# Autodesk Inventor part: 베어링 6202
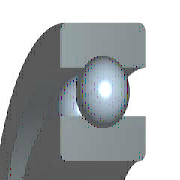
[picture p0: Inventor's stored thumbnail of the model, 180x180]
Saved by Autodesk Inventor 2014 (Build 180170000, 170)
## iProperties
IsCustomPart: 1
Created: 2015-09
Part Number: 베어링 6202
Material: 강철, 연강
Description: 깊은 그루브 볼 베어링
Document SubType Name: Modeling
Standard: KS B 2023
Designer: mduedu
Standards Organization: KS
Language: ko-KR
Size Designation: 6202 - 15 x 35 x 11
Categories: <MemberInstance><Categories><Category DisplayName="샤프트 부품" InternalName="7f7aeb1f-a693-4053-b835-cee3144e0d98" Mnemonic="SHFT"><Category DisplayName="베어링" Inter
Density: 7.86 g/cm^3
Mass: 45.8725 g
Surface Area: 51.5584 cm^2
Volume: 5.83619 cm^3
Appearance: 노란색
Author: mduedu
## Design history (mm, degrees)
sketch "스케치" dims "d0" = 5.2 (= -0.26 x WD + 0.26 x BD)
  geometry: L1 (2.9, 12.5)-(8.1, 12.5); L2 (5.5, 12.5)-(5.5, 9.9); L3 (5.5, 12.5)-(5.5, 15.1); L4 (3.568, 10.76)-(0, 10.76); L5 (0, 7.5)-(11, 7.5); L6 (3.568, 14.24)-(0, 14.24); L7 (0, 17.5)-(11, 17.5); L8 (11, 7.5)-(11, 10.76); L9 (7.432, 10.76)-(11, 10.76); L10 (7.432, 14.24)-(11, 14.24); L11 (11, 17.5)-(11, 14.24); L12 (-1.4, 0)-(8.4, 0) reference; L13 (0, -0.3)-(0, 5.3) reference
  constraints: 22 end point, 4 point on line, 2 collinear, 2 perpendicular, 2 symmetric about line, 1 midpoint, 1 parallel, 14 other
  dimensions: "d9" = 15 diameter of L5 L12 (= WD); "d11" = 35 diameter of L7 L12 (= BD); "d12" = 11 distance between parallel lines of L8 L13 (= KB); "d13" = 21.52 diameter of L9 L12 (= 0.326 x BD + 0.674 x WD)
revolve "본체" stored, may be unused: angle "d6" = 90 deg
revolve "볼" stored, may be unused: angle "d7" = 90 deg
pattern_circular "IDS_ARRAYBALL[SIMPL:T]" dims angle "d3" = 360 deg
body "Solid1"
fillet "모깎기1" dims "d1" = 0.6 (= KRS)
other parameters: "WD" = 15 [user parameter; used in 5 equation terms], "BD" = 35 [user parameter; used in 5 equation terms], "KB" = 11 [user parameter; used in 1 equation term], "KRS" = 0.6 [user parameter; used in 1 equation term], "d4" = 0, "d5" = 0, "d8" = 0, "d14" = 0, "d15" = 0, "BBA" = 0 [user parameter], "BC0" = 3750000 [user parameter], "BC" = 7800000 [user parameter], "BR" = 17.5 (= 0.5 x BD) [user parameter], "WR" = 7.5 (= 0.5 x WD) [user parameter]
